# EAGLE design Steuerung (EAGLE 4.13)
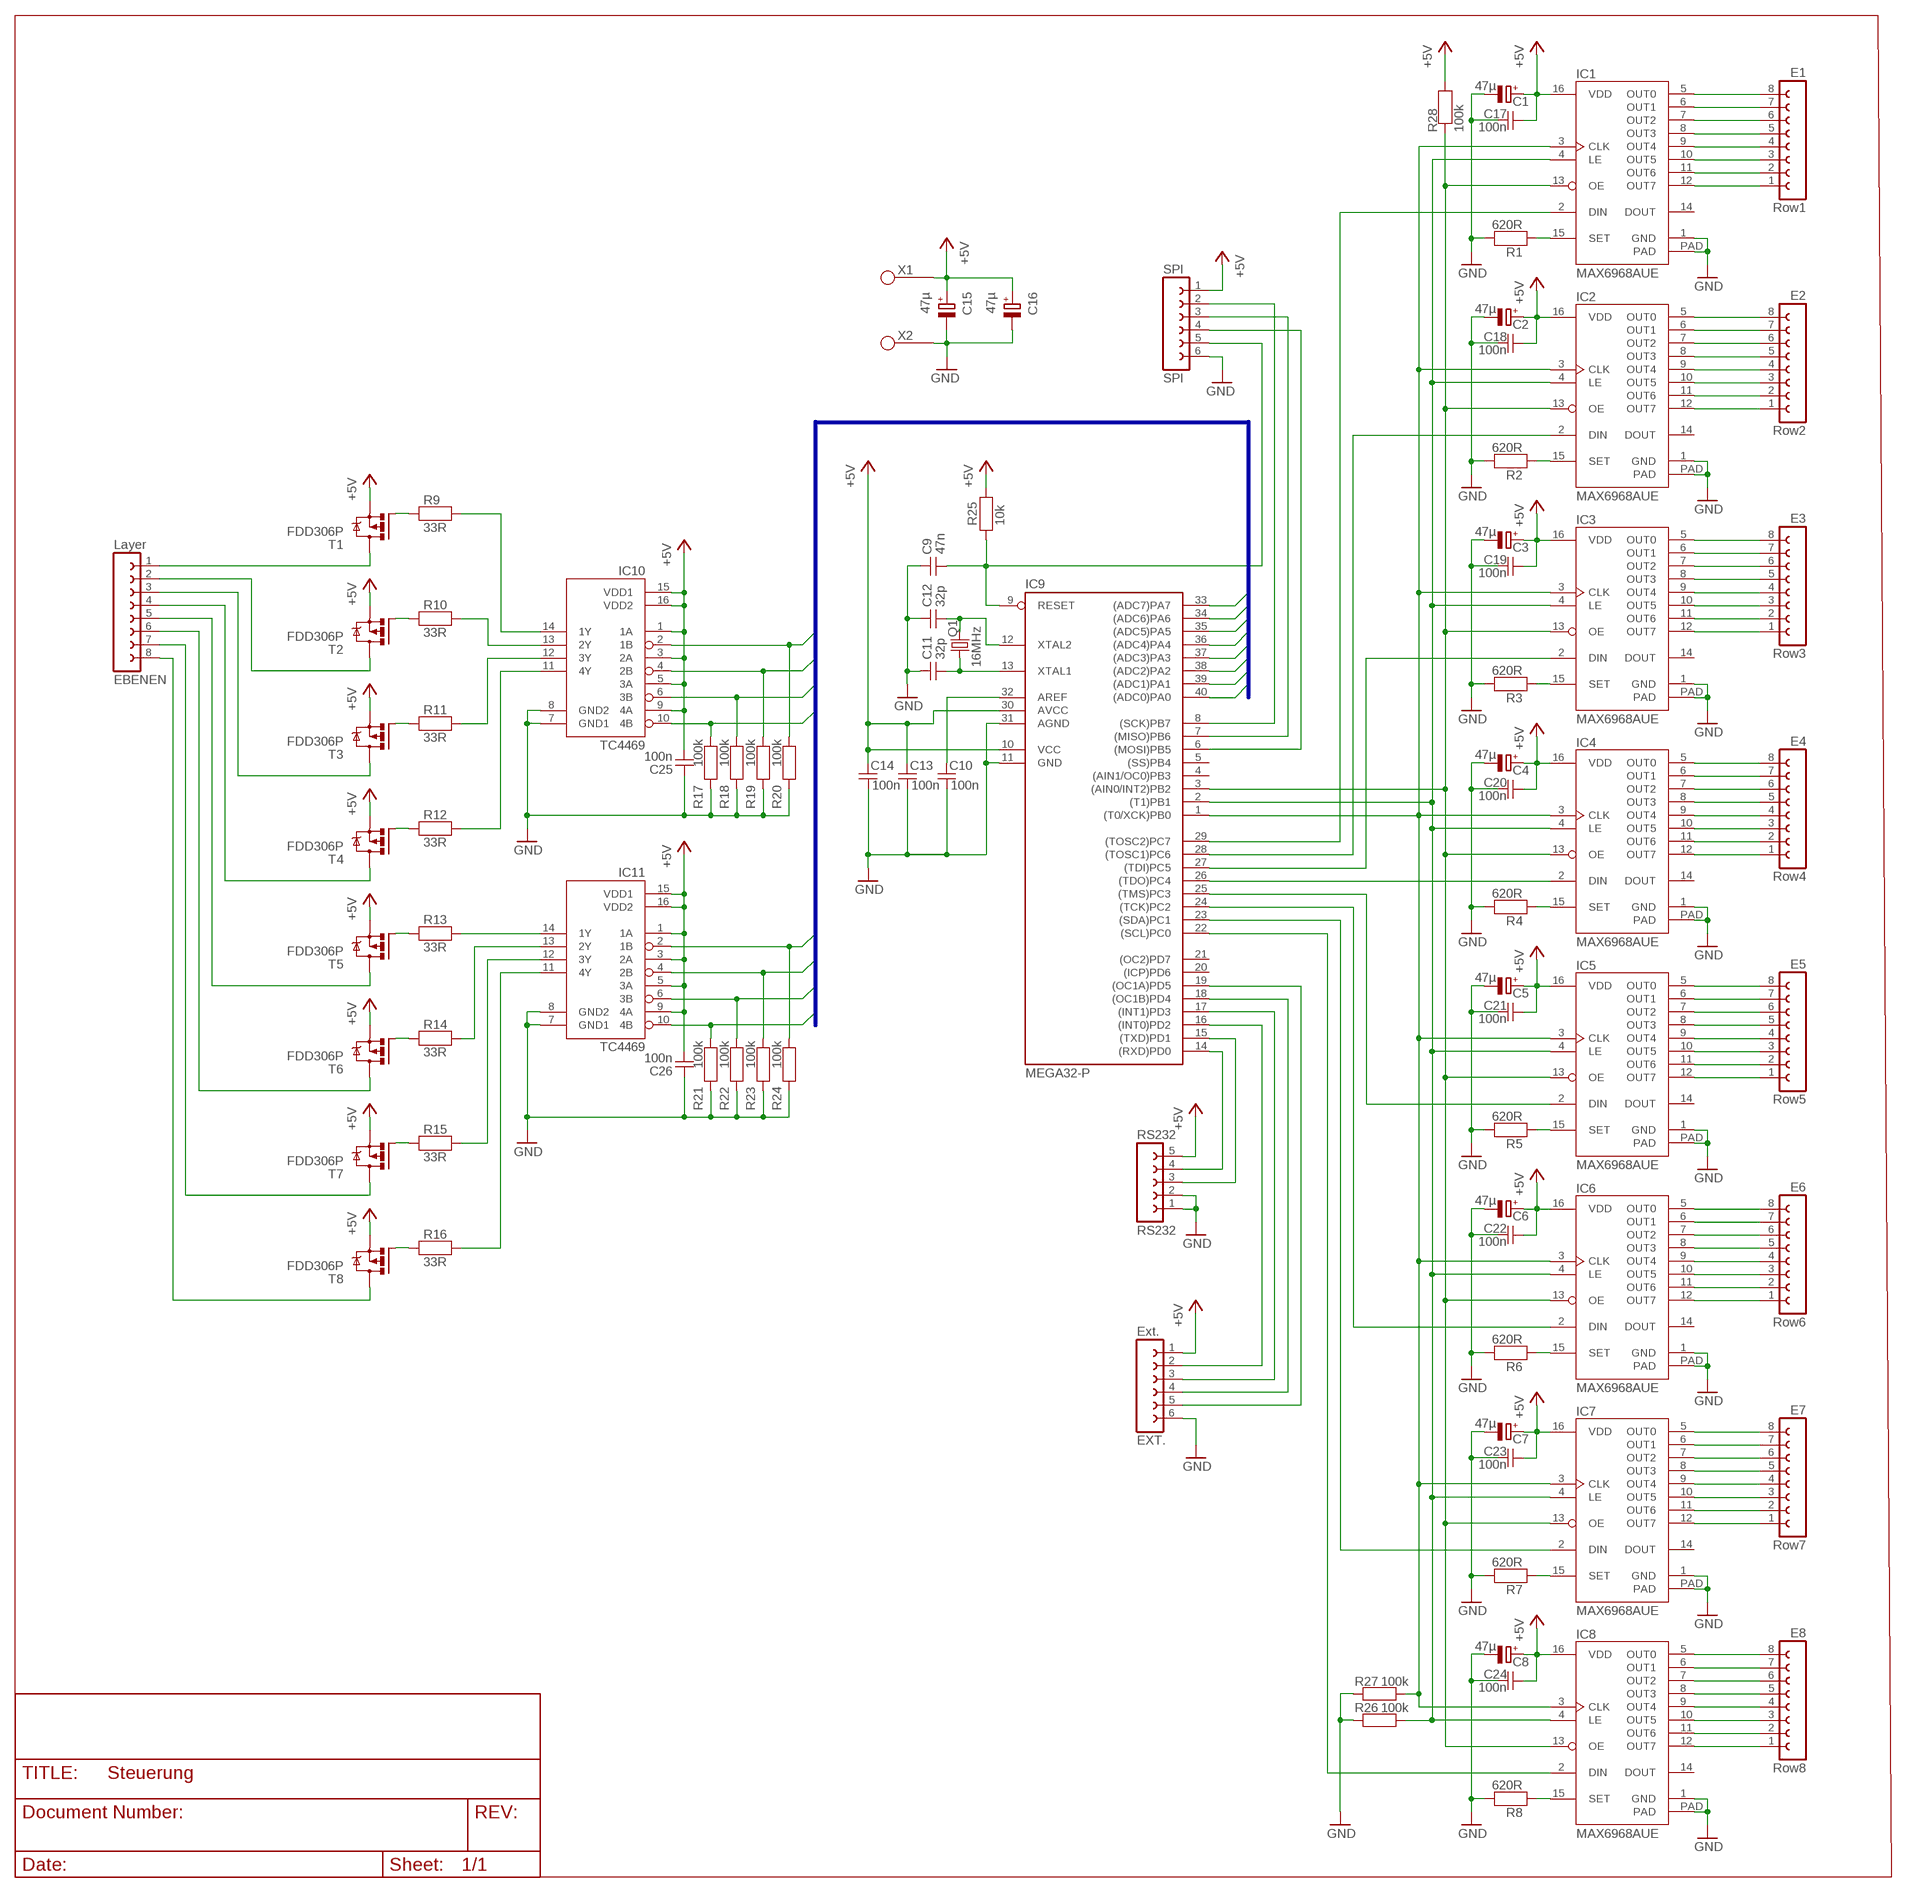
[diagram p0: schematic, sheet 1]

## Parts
C1  47µ  CPOL-EU153CLV-0505  [153CLV-0505]
C2  47µ  CPOL-EU153CLV-0505  [153CLV-0505]
C3  47µ  CPOL-EU153CLV-0505  [153CLV-0505]
C4  47µ  CPOL-EU153CLV-0505  [153CLV-0505]
C5  47µ  CPOL-EU153CLV-0505  [153CLV-0505]
C6  47µ  CPOL-EU153CLV-0505  [153CLV-0505]
C7  47µ  CPOL-EU153CLV-0505  [153CLV-0505]
C8  47µ  CPOL-EU153CLV-0505  [153CLV-0505]
C9  47n  C_SMD_0805  [SMD_0805]
C10  100n  C_SMD_0805  [SMD_0805]
C11  32p  C_SMD_0805  [SMD_0805]
C12  32p  C_SMD_0805  [SMD_0805]
C13  100n  C_SMD_0805  [SMD_0805]
C14  100n  C_SMD_0805  [SMD_0805]
C15  47µ  CPOL-EU153CLV-0505  [153CLV-0505]
C16  47µ  CPOL-EU153CLV-0505  [153CLV-0505]
C17  100n  C_SMD_0805  [SMD_0805]
C18  100n  C_SMD_0805  [SMD_0805]
C19  100n  C_SMD_0805  [SMD_0805]
C20  100n  C_SMD_0805  [SMD_0805]
C21  100n  C_SMD_0805  [SMD_0805]
C22  100n  C_SMD_0805  [SMD_0805]
C23  100n  C_SMD_0805  [SMD_0805]
C24  100n  C_SMD_0805  [SMD_0805]
C25  100n  C_SMD_0805  [SMD_0805]
C26  100n  C_SMD_0805  [SMD_0805]
E1  Row1  FE08W  [FE08W]
E2  Row2  FE08W  [FE08W]
E3  Row3  FE08W  [FE08W]
E4  Row4  FE08W  [FE08W]
E5  Row5  FE08W  [FE08W]
E6  Row6  FE08W  [FE08W]
E7  Row7  FE08W  [FE08W]
E8  Row8  FE08W  [FE08W]
EBENEN  Layer  FE08W  [FE08W]
EXT.  Ext.  FE06W  [FE06W]
IC1  MAX6968AUE  MAX6968  [TSSOP16_EP]
IC2  MAX6968AUE  MAX6968  [TSSOP16_EP]
IC3  MAX6968AUE  MAX6968  [TSSOP16_EP]
IC4  MAX6968AUE  MAX6968  [TSSOP16_EP]
IC5  MAX6968AUE  MAX6968  [TSSOP16_EP]
IC6  MAX6968AUE  MAX6968  [TSSOP16_EP]
IC7  MAX6968AUE  MAX6968  [TSSOP16_EP]
IC8  MAX6968AUE  MAX6968  [TSSOP16_EP]
IC9  MEGA32-P  [DIL40]
IC10  TC4469  TC4496_SOIC  [SO16L]
IC11  TC4469  TC4496_SOIC  [SO16L]
Q1  16MHz  CRYSTALHC49UP  [HC49UP]
R1  620R  R_SMD_0805  [SMD_0805]
R2  620R  R_SMD_0805  [SMD_0805]
R3  620R  R_SMD_0805  [SMD_0805]
R4  620R  R_SMD_0805  [SMD_0805]
R5  620R  R_SMD_0805  [SMD_0805]
R6  620R  R_SMD_0805  [SMD_0805]
R7  620R  R_SMD_0805  [SMD_0805]
R8  620R  R_SMD_0805  [SMD_0805]
R9  33R  R_SMD_0805  [SMD_0805]
R10  33R  R_SMD_0805  [SMD_0805]
R11  33R  R_SMD_0805  [SMD_0805]
R12  33R  R_SMD_0805  [SMD_0805]
R13  33R  R_SMD_0805  [SMD_0805]
R14  33R  R_SMD_0805  [SMD_0805]
R15  33R  R_SMD_0805  [SMD_0805]
R16  33R  R_SMD_0805  [SMD_0805]
R17  100k  R_SMD_0805  [SMD_0805]
R18  100k  R_SMD_0805  [SMD_0805]
R19  100k  R_SMD_0805  [SMD_0805]
R20  100k  R_SMD_0805  [SMD_0805]
R21  100k  R_SMD_0805  [SMD_0805]
R22  100k  R_SMD_0805  [SMD_0805]
R23  100k  R_SMD_0805  [SMD_0805]
R24  100k  R_SMD_0805  [SMD_0805]
R25  10k  R_SMD_0805  [SMD_0805]
R26  100k  R_SMD_0805  [SMD_0805]
R27  100k  R_SMD_0805  [SMD_0805]
R28  100k  R_SMD_0805  [SMD_0805]
RS232  RS232  FE05W  [FE05W]
SPI  SPI  FE06W  [FE06W]
T1  FDD306P  MOSFET-P  [DPAK]
T2  FDD306P  MOSFET-P  [DPAK]
T3  FDD306P  MOSFET-P  [DPAK]
T4  FDD306P  MOSFET-P  [DPAK]
T5  FDD306P  MOSFET-P  [DPAK]
T6  FDD306P  MOSFET-P  [DPAK]
T7  FDD306P  MOSFET-P  [DPAK]
T8  FDD306P  MOSFET-P  [DPAK]
X1  LOETANSCHLUSS_1,0  [LOETANSCHLUSS_1,0]
X2  LOETANSCHLUSS_1,0  [LOETANSCHLUSS_1,0]

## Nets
+5V: C1.+ C2.+ C3.+ C4.+ C5.+ C6.+ C7.+ C8.+ C13.1 C14.1 C15.+ C16.+ C17.2 C18.2 C19.2 C20.2 C21.2 C22.2 C23.2 C24.2 C25.2 C26.2 EXT..1 IC1.16(VDD) IC2.16(VDD) IC3.16(VDD) IC4.16(VDD) IC5.16(VDD) IC6.16(VDD) IC7.16(VDD) IC8.16(VDD) IC9.10(VCC) IC9.30(AVCC) IC10.1(1A) IC10.3(2A) IC10.5(3A) IC10.9(4A) IC10.15(VDD1) IC10.16(VDD2) IC11.1(1A) IC11.3(2A) IC11.5(3A) IC11.9(4A) IC11.15(VDD1) IC11.16(VDD2) R25.2 R28.2 RS232.5 SPI.1 T1.3(S) T2.3(S) T3.3(S) T4.3(S) T5.3(S) T6.3(S) T7.3(S) T8.3(S) X1.P$1
CLK: IC1.3(CLK) IC2.3(CLK) IC3.3(CLK) IC4.3(CLK) IC5.3(CLK) IC6.3(CLK) IC7.3(CLK) IC8.3(CLK) IC9.1((T0/XCK)PB0) R27.2
E0: IC9.40((ADC0)PA0) IC10.2(1B) R20.2
E1: IC9.39((ADC1)PA1) IC10.4(2B) R19.2
E2: IC9.38((ADC2)PA2) IC10.6(3B) R18.2
E3: IC9.37((ADC3)PA3) IC10.10(4B) R17.2
E4: IC9.36((ADC4)PA4) IC11.2(1B) R24.2
E5: IC9.35((ADC5)PA5) IC11.4(2B) R23.2
E6: IC9.34((ADC6)PA6) IC11.6(3B) R22.2
E7: IC9.33((ADC7)PA7) IC11.10(4B) R21.2
GND: C1.- C2.- C3.- C4.- C5.- C6.- C7.- C8.- C9.1 C10.2 C11.1 C12.1 C13.2 C14.2 C15.- C16.- C17.1 C18.1 C19.1 C20.1 C21.1 C22.1 C23.1 C24.1 C25.1 C26.1 EXT..6 IC1.1(GND) IC1.PAD IC2.1(GND) IC2.PAD IC3.1(GND) IC3.PAD IC4.1(GND) IC4.PAD IC5.1(GND) IC5.PAD IC6.1(GND) IC6.PAD IC7.1(GND) IC7.PAD IC8.1(GND) IC8.PAD IC9.11(GND) IC9.31(AGND) IC10.7(GND1) IC10.8(GND2) IC11.7(GND1) IC11.8(GND2) R1.2 R2.2 R3.2 R4.2 R5.2 R6.2 R7.2 R8.2 R17.1 R18.1 R19.1 R20.1 R21.1 R22.1 R23.1 R24.1 R26.1 R27.1 RS232.1 RS232.2 SPI.6 X2.P$1
LE: IC1.4(LE) IC2.4(LE) IC3.4(LE) IC4.4(LE) IC5.4(LE) IC6.4(LE) IC7.4(LE) IC8.4(LE) IC9.2((T1)PB1) R26.2
MISO: IC9.7((MISO)PB6) SPI.3
MOSI: IC9.6((MOSI)PB5) SPI.4
N$1: EBENEN.1 T1.2(D)
N$2: R9.1 T1.1(G)
N$3: R10.1 T2.1(G)
N$4: EBENEN.2 T2.2(D)
N$5: IC1.15(SET) R1.1
N$6: R11.1 T3.1(G)
N$7: EBENEN.3 T3.2(D)
N$8: R12.1 T4.1(G)
N$9: EBENEN.4 T4.2(D)
N$10: IC3.15(SET) R3.1
N$11: R13.1 T5.1(G)
N$12: EBENEN.5 T5.2(D)
N$13: R14.1 T6.1(G)
N$14: C11.2 IC9.13(XTAL1) Q1.1
N$15: IC4.15(SET) R4.1
N$16: IC1.2(DIN) IC9.29((TOSC2)PC7)
N$17: C12.2 IC9.12(XTAL2) Q1.2
N$18: E1.8 IC1.5(OUT0)
N$19: C10.1 IC9.32(AREF)
N$20: IC2.2(DIN) IC9.28((TOSC1)PC6)
N$21: IC3.2(DIN) IC9.27((TDI)PC5)
N$22: IC4.2(DIN) IC9.26((TDO)PC4)
N$23: IC2.15(SET) R2.1
N$24: IC5.2(DIN) IC9.25((TMS)PC3)
N$25: IC6.2(DIN) IC9.24((TCK)PC2)
N$26: IC5.15(SET) R5.1
N$27: IC7.2(DIN) IC9.23((SDA)PC1)
N$28: IC8.2(DIN) IC9.22((SCL)PC0)
N$29: IC6.15(SET) R6.1
N$30: EBENEN.6 T6.2(D)
N$31: R15.1 T7.1(G)
N$32: IC7.15(SET) R7.1
N$33: IC9.14((RXD)PD0) RS232.4
N$34: IC9.15((TXD)PD1) RS232.3
N$35: IC8.15(SET) R8.1
N$36: EBENEN.7 T7.2(D)
N$37: R16.1 T8.1(G)
N$38: EBENEN.8 T8.2(D)
N$39: IC10.14(1Y) R9.2
N$40: IC10.13(2Y) R10.2
N$41: IC10.12(3Y) R11.2
N$42: IC10.11(4Y) R12.2
N$43: IC11.14(1Y) R13.2
N$44: IC11.13(2Y) R14.2
N$45: IC11.12(3Y) R15.2
N$46: IC11.11(4Y) R16.2
N$47: E1.7 IC1.6(OUT1)
N$48: E1.6 IC1.7(OUT2)
N$49: E1.5 IC1.8(OUT3)
N$50: E1.4 IC1.9(OUT4)
N$51: E1.3 IC1.10(OUT5)
N$52: E1.2 IC1.11(OUT6)
N$53: E1.1 IC1.12(OUT7)
N$54: E2.8 IC2.5(OUT0)
N$55: E2.7 IC2.6(OUT1)
N$56: E2.6 IC2.7(OUT2)
N$57: E2.5 IC2.8(OUT3)
N$58: E2.4 IC2.9(OUT4)
N$59: E2.3 IC2.10(OUT5)
N$60: E2.2 IC2.11(OUT6)
N$61: E2.1 IC2.12(OUT7)
N$62: E3.8 IC3.5(OUT0)
N$63: E3.7 IC3.6(OUT1)
N$64: E3.6 IC3.7(OUT2)
N$65: E3.5 IC3.8(OUT3)
N$66: E3.4 IC3.9(OUT4)
N$67: E3.3 IC3.10(OUT5)
N$68: E3.2 IC3.11(OUT6)
N$69: E3.1 IC3.12(OUT7)
N$70: E4.8 IC4.5(OUT0)
N$71: E4.7 IC4.6(OUT1)
N$72: E4.6 IC4.7(OUT2)
N$73: E4.5 IC4.8(OUT3)
N$74: E4.4 IC4.9(OUT4)
N$75: E4.3 IC4.10(OUT5)
N$76: E4.2 IC4.11(OUT6)
N$77: E4.1 IC4.12(OUT7)
N$78: E5.8 IC5.5(OUT0)
N$79: E5.7 IC5.6(OUT1)
N$80: E5.6 IC5.7(OUT2)
N$81: E5.5 IC5.8(OUT3)
N$82: E5.4 IC5.9(OUT4)
N$83: E5.3 IC5.10(OUT5)
N$84: E5.2 IC5.11(OUT6)
N$85: E5.1 IC5.12(OUT7)
N$86: E6.8 IC6.5(OUT0)
N$87: E6.7 IC6.6(OUT1)
N$88: E6.6 IC6.7(OUT2)
N$89: E6.5 IC6.8(OUT3)
N$90: E6.4 IC6.9(OUT4)
N$91: E6.3 IC6.10(OUT5)
N$92: E6.2 IC6.11(OUT6)
N$93: E6.1 IC6.12(OUT7)
N$94: E7.7 IC7.6(OUT1)
N$95: E7.8 IC7.5(OUT0)
N$96: E7.6 IC7.7(OUT2)
N$97: E7.5 IC7.8(OUT3)
N$98: E7.4 IC7.9(OUT4)
N$99: E7.3 IC7.10(OUT5)
N$100: E7.2 IC7.11(OUT6)
N$101: E7.1 IC7.12(OUT7)
N$102: E8.8 IC8.5(OUT0)
N$103: E8.7 IC8.6(OUT1)
N$104: E8.6 IC8.7(OUT2)
N$105: E8.5 IC8.8(OUT3)
N$106: E8.4 IC8.9(OUT4)
N$107: E8.3 IC8.10(OUT5)
N$108: E8.2 IC8.11(OUT6)
N$109: E8.1 IC8.12(OUT7)
N$112: EXT..2 IC9.16((INT0)PD2)
N$113: EXT..3 IC9.17((INT1)PD3)
N$114: EXT..4 IC9.18((OC1B)PD4)
N$115: EXT..5 IC9.19((OC1A)PD5)
OE: IC1.13(OE) IC2.13(OE) IC3.13(OE) IC4.13(OE) IC5.13(OE) IC6.13(OE) IC7.13(OE) IC8.13(OE) IC9.3((AIN0/INT2)PB2) R28.1
RESET: C9.2 IC9.9(RESET) R25.1 SPI.5
SCK: IC9.8((SCK)PB7) SPI.2
Unconnected: IC1.14(DOUT) IC2.14(DOUT) IC3.14(DOUT) IC4.14(DOUT) IC5.14(DOUT) IC6.14(DOUT) IC7.14(DOUT) IC8.14(DOUT) IC9.4((AIN1/OC0)PB3) IC9.5((SS)PB4) IC9.20((ICP)PD6) IC9.21((OC2)PD7)

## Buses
EBENEN:E[0..7]

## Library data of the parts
C1-C8 C15 C16 = rcl:CPOL-EU: POLARIZED CAPACITOR, European symbol
C9-C14 C17-C26 = LEMF-passiv:C: KONDENSATOR
E1-E8 EBENEN = con-lsta:FE08W: FEMALE HEADER
EXT. SPI = con-lsta:FE06W: FEMALE HEADER
IC1-IC8 = maxim:MAX6968
IC9 = avr-5-4.16:MEGA32-P: MICROCONTROLLER 32 Kbytes FLASH 2 Kbytes SRAM 1 Kbytes EEPROM USART 8-channel 10 bit ADC
IC10 IC11 = microchip:TC4496_SOIC
Q1 = LEMF-Mix:CRYSTAL: CRYSTAL
R1-R28 = LEMF-passiv:R: Widerstand
RS232 = con-lsta:FE05W: FEMALE HEADER
T1-T8 = transistor-fet:MOSFET-P
X1 X2 = LEMF-Con:LOETANSCHLUSS

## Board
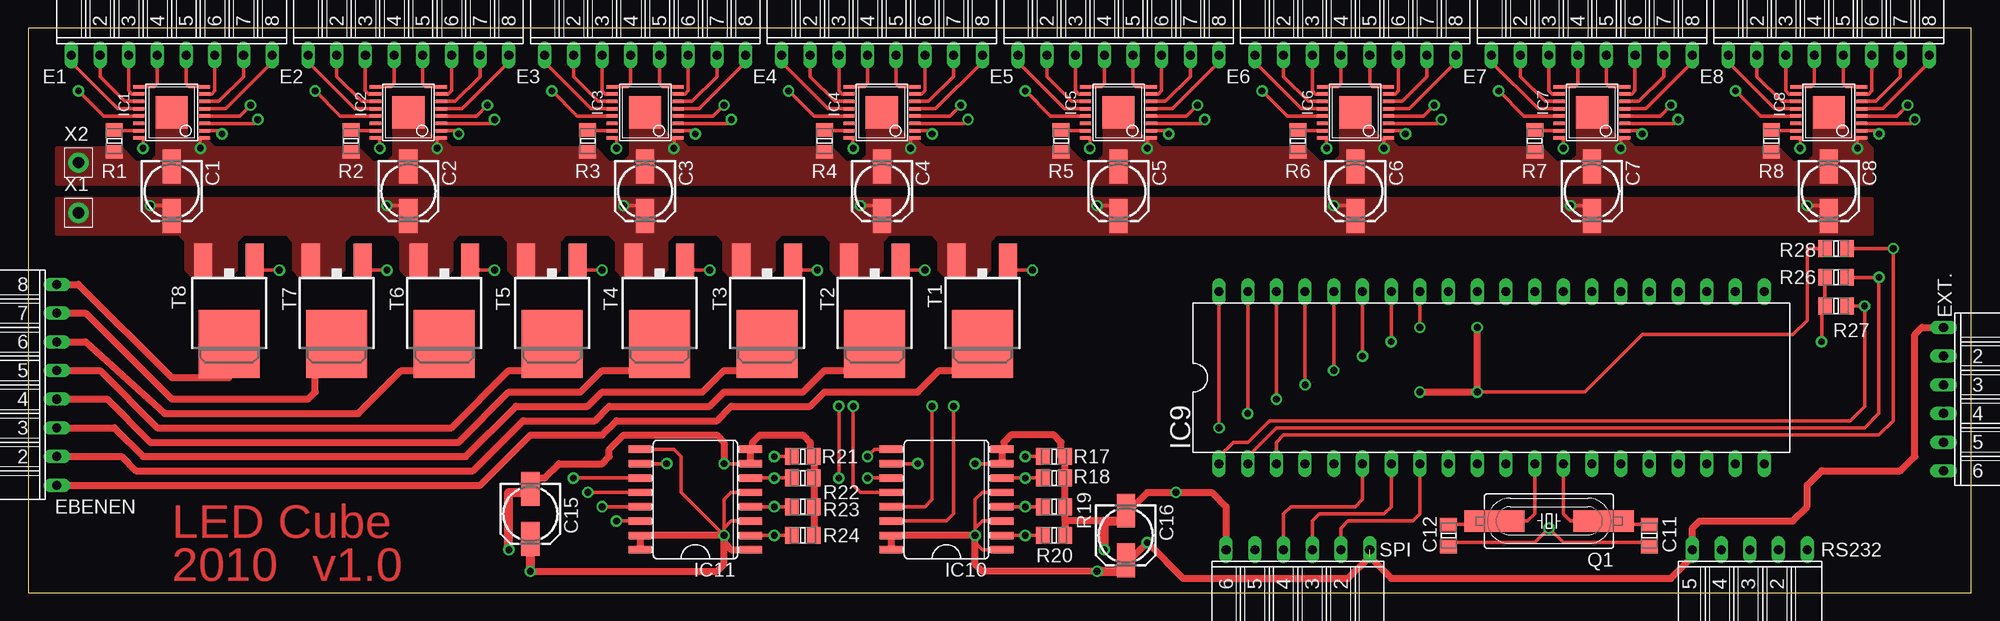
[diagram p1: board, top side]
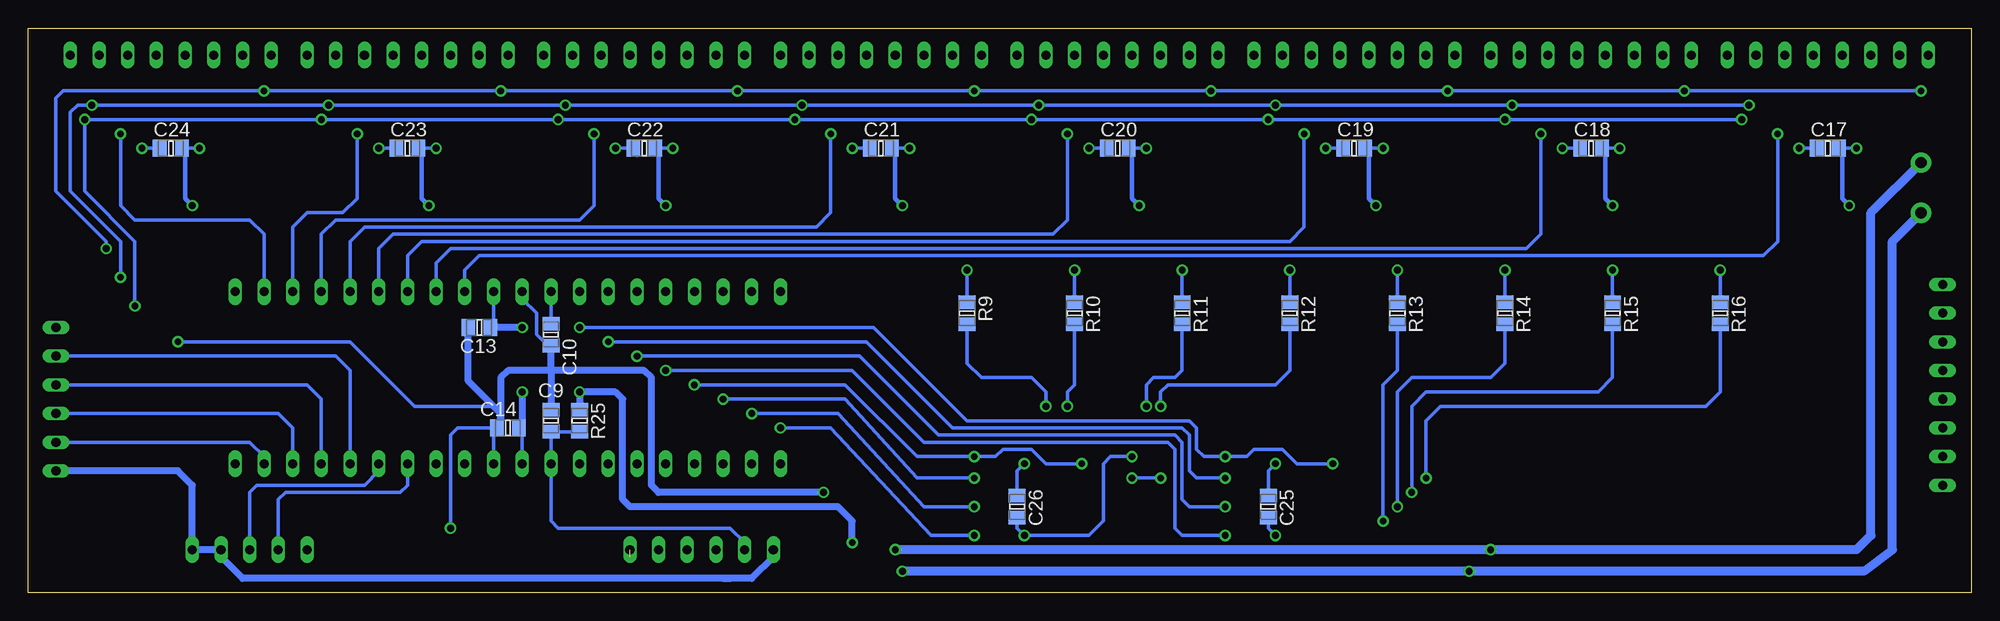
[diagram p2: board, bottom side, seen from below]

Size 172 x 50 mm. Coordinates in mm from the lower left corner, seen from the top.
Outline: 0,0 172,0 172,50 0,50 0,0
Copper layers (1*16): Top 0.035mm / dielectric 1.5mm / Bottom 0.035mm
Design rules "qp_designrules_8mil": minimum track width 8mil, minimum drill 20mil, track to track 8mil, track to pad 8mil, pad to pad 8mil, via to via 8mil, smd to smd 8mil, copper to edge 20mil, drill to drill 20mil, minimum pad ring 8mil, minimum via ring 8mil, stop-mask expansion 0mil, vias tented up to drill 0mil, thermal gap 10mil

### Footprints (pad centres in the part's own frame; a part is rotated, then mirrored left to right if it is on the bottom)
153CLV-0505 = smd 3 x 1.6: + 2.2,0; - -2.2,0
SMD_0805 = smd 1.2 x 1.5: 1 -0.975,0; 2 0.975,0
FE08W = drill 0.8 long: 1 -8.89,0; 2 -6.35,0; 3 -3.81,0; 4 -1.27,0; 5 1.27,0; 6 3.81,0; 7 6.35,0; 8 8.89,0
FE06W = drill 0.8 long: 1 -6.35,0; 2 -3.81,0; 3 -1.27,0; 4 1.27,0; 5 3.81,0; 6 6.35,0
TSSOP16_EP = smd 0.305 x 0.991: 1 -2.275,-2.918; 2 -1.625,-2.918; 3 -0.975,-2.918; 4 -0.325,-2.918; 5 0.325,-2.918; 6 0.975,-2.918; 7 1.625,-2.918; 8 2.275,-2.918; 9 2.275,2.918; 10 1.625,2.918; 11 0.975,2.918; 12 0.325,2.918; 13 -0.325,2.918; 14 -0.975,2.918; 15 -1.625,2.918; 16 -2.275,2.918 | smd 2.85 x 2.85: PAD 0,0
DIL40 = drill 0.8 long: 1 -24.13,-7.62; 2 -21.59,-7.62; 3 -19.05,-7.62; 4 -16.51,-7.62; 5 -13.97,-7.62; 6 -11.43,-7.62; 7 -8.89,-7.62; 8 -6.35,-7.62; 9 -3.81,-7.62; 10 -1.27,-7.62; 11 1.27,-7.62; 12 3.81,-7.62; 13 6.35,-7.62; 14 8.89,-7.62; 15 11.43,-7.62; 16 13.97,-7.62; 17 16.51,-7.62; 18 19.05,-7.62; 19 21.59,-7.62; 20 24.13,-7.62; 21 24.13,7.62; 22 21.59,7.62; 23 19.05,7.62; 24 16.51,7.62; 25 13.97,7.62; 26 11.43,7.62; 27 8.89,7.62; 28 6.35,7.62; 29 3.81,7.62; 30 1.27,7.62; 31 -1.27,7.62; 32 -3.81,7.62; 33 -6.35,7.62; 34 -8.89,7.62; 35 -11.43,7.62; 36 -13.97,7.62; 37 -16.51,7.62; 38 -19.05,7.62; 39 -21.59,7.62; 40 -24.13,7.62
SO16L = smd 0.66 x 2.032: 1 -4.445,-4.902; 2 -3.175,-4.902; 3 -1.905,-4.902; 4 -0.635,-4.902; 5 0.635,-4.902; 6 1.905,-4.902; 7 3.175,-4.902; 8 4.445,-4.902; 9 4.445,4.902; 10 3.175,4.902; 11 1.905,4.902; 12 0.635,4.902; 13 -0.635,4.902; 14 -1.905,4.902; 15 -3.175,4.902; 16 -4.445,4.902
HC49UP = smd 5.334 x 1.93: 1 -4.826,0; 2 4.826,0
FE05W = drill 0.8 long: 1 -5.08,0; 2 -2.54,0; 3 0,0; 4 2.54,0; 5 5.08,0
DPAK = smd 1.6 x 3: 1 -2.28,-5.31; 3 2.28,-5.31 | smd 5.4 x 6: 2 0,2.096
LOETANSCHLUSS_1,0 = drill 1 pad 1.8 round: P$1 0,0

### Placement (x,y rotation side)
C1  12.7,35.56 270 top
C2  33.66,35.56 270 top
C3  54.61,35.56 270 top
C4  75.56,35.56 270 top
C5  96.52,35.56 270 top
C6  117.47,35.56 270 top
C7  138.43,35.56 270 top
C8  159.38,35.56 270 top
C9  125.73,15.24 270 bottom
C10  125.73,22.86 270 bottom
C11  143.51,5.08 90 top
C12  125.73,5.08 90 top
C13  132.08,23.5 180 bottom
C14  129.54,14.61 180 bottom
C15  44.45,6.99 270 top
C16  97.16,5.08 270 top
C17  12.7,39.37 0 bottom
C18  33.66,39.37 0 bottom
C19  54.61,39.37 0 bottom
C20  75.56,39.37 0 bottom
C21  96.52,39.37 0 bottom
C22  117.47,39.37 0 bottom
C23  138.43,39.37 0 bottom
C24  159.38,39.37 0 bottom
C25  62.23,7.62 270 bottom
C26  84.45,7.62 270 bottom
E1  12.7,47.62 0 top
E2  33.66,47.62 0 top
E3  54.61,47.62 0 top
E4  75.56,47.62 0 top
E5  96.52,47.62 0 top
E6  117.47,47.62 0 top
E7  138.43,47.62 0 top
E8  159.38,47.62 0 top
EBENEN  2.54,18.41 90 top
EXT.  169.54,17.14 270 top
IC1  12.7,42.55 90 top
IC2  33.66,42.55 90 top
IC3  54.61,42.55 90 top
IC4  75.56,42.55 90 top
IC5  96.52,42.55 90 top
IC6  117.47,42.55 90 top
IC7  138.43,42.55 90 top
IC8  159.38,42.55 90 top
IC9  129.54,19.05 0 top
IC10  81.28,8.26 90 top
IC11  59.05,8.26 90 top
Q1  134.62,6.35 180 top
R1  7.62,40.01 270 top
R2  28.57,40.01 270 top
R3  49.53,40.01 270 top
R4  70.48,40.01 270 top
R5  91.44,40.01 270 top
R6  112.39,40.01 270 top
R7  133.35,40.01 270 top
R8  154.31,40.01 270 top
R9  88.9,24.77 270 bottom
R10  79.38,24.77 270 bottom
R11  69.85,24.77 270 bottom
R12  60.33,24.77 270 bottom
R13  50.8,24.77 270 bottom
R14  41.27,24.77 270 bottom
R15  31.75,24.77 270 bottom
R16  22.23,24.77 270 bottom
R17  90.81,12.06 180 top
R18  90.81,10.16 180 top
R19  90.81,7.62 180 top
R20  90.81,5.08 180 top
R21  68.58,12.06 180 top
R22  68.58,10.16 180 top
R23  68.58,7.62 180 top
R24  68.58,5.08 180 top
R25  123.19,15.24 90 bottom
R26  160.02,27.94 0 top
R27  160.02,25.4 0 top
R28  160.02,30.48 180 top
RS232  152.4,3.81 180 top
SPI  112.39,3.81 180 top
T1  84.45,24.13 180 top
T2  74.93,24.13 180 top
T3  65.41,24.13 180 top
T4  55.88,24.13 180 top
T5  46.35,24.13 180 top
T6  36.83,24.13 180 top
T7  27.3,24.13 180 top
T8  17.78,24.13 180 top
X1  4.45,33.66 0 top
X2  4.45,38.1 0 top

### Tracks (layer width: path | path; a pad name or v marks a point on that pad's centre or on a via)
+5V  (via drill 0.6)  (1 unrouted)
  Top 0.3: IC3.16 52.07,40.27 v52.07,39.37 | IC1.16 10.16,40.27 v10.16,39.37 | IC2.16 31.11,40.27 v31.11,39.37 | IC4.16 73.03,40.27 v73.03,39.37 | IC5.16 93.98,40.27 v93.98,39.37 | IC6.16 114.94,40.27 v114.94,39.37 | IC7.16 135.89,40.27 v135.89,39.37 | IC8.16 156.84,40.27 v156.84,39.37 | v10.79,34.29 12.7,34.29 | v31.75,34.29 33.66,34.29 C2.+ 33.66,33.02 | v52.7,34.29 54.61,34.29 C3.+ | v73.66,34.29 75.56,34.29 C4.+ 75.56,33.02 | v94.61,34.29 96.52,34.29 C5.+ 96.52,33.02 | v115.57,34.29 117.47,34.29 C6.+ 117.47,33.02 | v136.53,34.29 138.43,34.29 C7.+ 138.43,33.02 | v157.48,34.29 159.38,34.29 C8.+ 159.38,33.02 | IC11.15 53.98,5.08 | IC11.16 54.61,3.81 | 54.61,12.7 IC11.9 57.15,12.7 57.78,12.06 57.78,8.89 v61.59,5.08 | IC11.3 62.23,6.35 61.59,5.71 v61.59,5.08 | IC11.5 62.23,8.89 61.59,8.26 v61.59,5.08 | IC10.15 76.2,5.08 76.38,4.9 | IC10.1 84.45,3.81 83.82,4.45 v83.82,5.08 | IC10.3 84.45,6.35 83.82,5.71 v83.82,5.08 | IC10.5 84.45,8.89 83.82,8.26 v83.82,5.08 | v74.3,12.06 74.93,12.7 IC10.9 | R28.2 157.48,30.48 157.48,24.13 156.21,22.86 142.88,22.86 137.79,17.78 v128.27,17.78
  Top 0.6: v61.59,5.08 IC11.15 IC11.16 | IC11.1 62.23,3.81 61.59,4.45 v61.59,5.08 | 76.38,4.9 IC10.16 | IC10.15 v83.82,5.08 83.82,2.54 84.45,1.91 v94.61,1.91 | C15.+ 44.45,5.08 | v61.59,5.08 61.59,2.54 60.96,1.91 v44.45,1.91 | v123.19,17.78 v128.27,17.78 v128.27,23.5 | C16.+ 97.5,2.88 v99.06,4.45 102.23,1.27 116.84,1.27 118.75,3.17 120.65,1.27 145.41,1.27 147.32,3.17 RS232.5 147.32,5.71 147.96,6.35 156.21,6.35 157.48,7.62 157.48,9.53 158.75,10.79 165.74,10.79 167,12.06 167,22.86 167.64,23.5 EXT..1
  Top 0.8: v94.61,1.91 97.16,1.91 C16.+ | v44.45,1.91 C15.+
  Bottom 0.3: 95.89,39.37 C21.2 95.25,39.37 v93.98,39.37 | v52.07,39.37 53.34,39.37 C19.2 | 12.06,39.37 C17.2 11.43,39.37 v10.16,39.37 | 33.02,39.37 C18.2 32.38,39.37 v31.11,39.37 | 74.93,39.37 C20.2 74.3,39.37 v73.03,39.37 | v114.94,39.37 116.2,39.37 C22.2 | 137.79,39.37 C23.2 137.16,39.37 v135.89,39.37 | 158.75,39.37 C24.2 158.12,39.37 v156.84,39.37 | C25.2 62.23,5.71 v61.59,5.08 | 84.45,6.99 C26.2 84.45,5.71 v83.82,5.08 78.11,5.08 76.83,6.35 76.83,11.43 76.2,12.06 v74.3,12.06 | C14.1 128.27,14.61 IC9.10 | 130.81,23.5 IC9.30
  Bottom 0.4: v10.79,34.29 11.43,34.92 11.43,39.37 | v31.75,34.29 32.38,34.92 32.38,39.37 | v52.7,34.29 53.34,34.92 53.34,39.37 | v73.66,34.29 74.3,34.92 74.3,39.37 | v94.61,34.29 95.25,34.92 95.25,39.37 | v115.57,34.29 116.2,34.92 116.2,39.37 | v136.53,34.29 137.16,34.92 137.16,39.37 | v157.48,34.29 158.12,34.92 158.12,39.37
  Bottom 0.6: v128.27,17.78 128.27,14.61 | C13.1 130.81,23.5 v128.27,23.5 | R25.2 v123.19,17.78 120.02,17.78 119.38,17.14 119.38,8.26 118.75,7.62 100.33,7.62 99.06,6.35 v99.06,4.45
  Bottom 0.8: X1.P$1 6.99,31.11 6.99,3.81 9.53,1.91 v44.45,1.91 v94.61,1.91
  pour Top (no thermals): 2.54,34.92 163.19,34.92 163.19,31.75 2.54,31.75
  pour Top (no thermals): 24.13,27.94 23.5,28.57 23.5,31.11 22.86,31.75 19.05,31.75 18.41,31.11 18.41,28.57 17.78,27.94 14.61,27.94 13.97,28.57 13.97,31.11 13.34,31.75 6.99,31.75 6.99,32.38 85.72,32.38 85.72,31.75 85.09,31.11 85.09,28.57 84.45,27.94 81.28,27.94 80.64,28.57 80.64,31.11 80.01,31.75 76.2,31.75 75.56,31.11 75.56,28.57 74.93,27.94 71.75,27.94 71.12,28.57 71.12,31.11 70.48,31.75 66.67,31.75 66.04,31.11 66.04,28.57 65.41,27.94 62.23,27.94 61.59,28.57 61.59,31.11 60.96,31.75 57.15,31.75 56.52,31.11 56.52,28.57 55.88,27.94 52.7,27.94 52.07,28.57 52.07,31.11 51.44,31.75 47.62,31.75 46.99,31.11 46.99,28.57 46.35,27.94 43.18,27.94 42.55,28.57 42.55,31.11 41.91,31.75 38.1,31.75 37.47,31.11 37.47,28.57 36.83,27.94 33.66,27.94 33.02,28.57 33.02,31.11 32.38,31.75 28.57,31.75 27.94,31.11 27.94,28.57 27.3,27.94
CLK  (via drill 0.6, 0.6 pad 0.45)
  Top 0.3: IC1.3 19.98,41.57 v20.32,41.91 | IC2.3 40.94,41.57 v41.27,41.91 | IC3.3 61.89,41.57 v62.23,41.91 | IC4.3 82.84,41.57 v83.19,41.91 | IC5.3 103.8,41.57 v104.14,41.91 | IC6.3 124.75,41.57 v125.09,41.91 | IC7.3 145.71,41.57 v146.05,41.91 | IC8.3 166.66,41.57 v167,41.91 | IC9.1 105.41,12.06 106.68,13.34 107.95,13.34 109.86,15.24 161.29,15.24 162.56,16.51 v162.56,25.4 R27.2
  Bottom 0.3: v20.32,41.91 v41.27,41.91 v62.23,41.91 v83.19,41.91 v104.14,41.91 v125.09,41.91 v146.05,41.91 v167,41.91 167,35.56 162.56,31.11 v162.56,25.4
E0  (via drill 0.6)
  Top 0.3: 90.17,5.08 R20.2 v88.27,5.08 IC10.2 | v105.41,14.61 IC9.40
  Bottom 0.3: v88.27,5.08 92.08,5.08 100.97,14.61 v105.41,14.61
E1  (via drill 0.6)
  Top 0.3: 90.17,7.62 R19.2 v88.27,7.62 IC10.4 | v107.95,15.88 IC9.39
  Bottom 0.3: v88.27,7.62 92.71,7.62 100.33,15.88 v107.95,15.88
E2  (via drill 0.6)
  Top 0.3: 90.17,10.16 R18.2 v88.27,10.16 IC10.6 | v110.49,17.14 IC9.38
  Bottom 0.3: v88.27,10.16 93.34,10.16 99.69,17.14 v110.49,17.14
E3  (via drill 0.6)
  Top 0.3: v88.27,12.06 R17.2 | 76.2,11.43 IC10.10 v78.74,11.43 | v113.03,18.41 IC9.37
  Bottom 0.3: v78.74,11.43 81.92,11.43 83.19,12.7 85.72,12.7 86.36,12.06 v88.27,12.06 93.34,12.06 99.69,18.41 v113.03,18.41
E4  (via drill 0.6)
  Top 0.3: IC11.2 v66.04,5.08 R24.2 | v115.57,19.68 IC9.36
  Bottom 0.3: v66.04,5.08 69.85,5.08 70.48,5.71 70.48,12.7 71.12,13.34 92.71,13.34 99.06,19.68 v115.57,19.68
E5  (via drill 0.6)
  Top 0.3: IC11.4 v66.04,7.62 R23.2 67.94,7.62 | v118.11,20.95 IC9.35
  Bottom 0.3: v66.04,7.62 69.22,7.62 69.85,8.26 69.85,13.34 70.48,13.97 91.44,13.97 98.42,20.95 v118.11,20.95
E6  (via drill 0.6)
  Top 0.3: IC11.6 v66.04,10.16 R22.2 67.94,10.16 | v120.65,22.23 IC9.34
  Bottom 0.3: v66.04,10.16 68.58,10.16 69.22,10.79 69.22,13.97 69.85,14.61 90.17,14.61 97.79,22.23 v120.65,22.23
E7  (via drill 0.6)
  Top 0.3: v66.04,12.06 R21.2 | 53.98,11.43 IC11.10 v56.52,11.43 | v123.19,23.5 IC9.33
  Bottom 0.3: v56.52,11.43 59.69,11.43 60.96,12.7 63.5,12.7 64.14,12.06 v66.04,12.06 67.94,12.06 68.58,12.7 68.58,14.61 69.22,15.24 88.9,15.24 97.16,23.5 v123.19,23.5
GND  (via drill 0.6)
  Top 0.3: IC3.1 57.15,40.27 v57.15,39.37 | IC1.1 15.24,40.27 v15.24,39.37 | IC2.1 36.2,40.27 v36.2,39.37 | IC4.1 78.11,40.27 v78.11,39.37 | IC5.1 99.06,40.27 v99.06,39.37 | IC6.1 120.02,40.27 v120.02,39.37 | IC7.1 140.97,40.27 v140.97,39.37 | IC8.1 161.93,40.27 v161.93,39.37 | 64.14,12.7 IC11.8 63.5,12.7 | 64.14,11.43 IC11.7 v61.59,11.43 | 86.18,11.61 86.36,11.43 IC10.7 v83.82,11.43 | 159.38,25.4 R27.1 | R26.1 159.04,25.74 159.38,25.4 | C11.1 143.51,4.45 135.89,4.45 v134.62,5.71 133.35,4.45 125.73,4.45 C12.1 | 159.38,25.4 158.75,25.4 v158.75,22.23 | 85.72,12.7 IC10.8 86.36,12.7 | R17.1 91.44,12.06 | 44.45,8.89 44.45,10.16
  Top 0.6: IC11.7 IC11.8 | IC10.8 86.18,11.61 | 64.14,12.7 64.14,13.34 64.77,13.97 68.58,13.97 69.22,13.34 69.22,12.06 R21.1 69.56,10.46 69.85,10.16 R22.1 69.56,7.96 69.85,7.62 R23.1 69.56,5.42 69.85,5.08 R24.1 | R17.1 91.78,10.5 92.08,10.16 R18.1 91.78,7.96 92.08,7.62 R19.1 91.78,6.35 | R20.1 92.08,5.08 91.78,5.38 91.78,6.35 | 95.25,6.35 91.78,6.35 | 44.45,10.16 45.72,10.16 46.99,11.43 50.8,11.43 51.44,12.06 51.44,12.7 52.7,13.97 60.96,13.97 61.59,13.34 v61.59,11.43 | 86.36,12.7 86.36,13.34 87,13.97 90.81,13.97 91.44,13.34 91.44,12.06 | C11.1 143.51,3.81 143.22,4.11 | 97.16,6.99 99.06,8.89 v101.6,8.89 104.78,8.89 106.05,7.62 SPI.6
  Top 0.8: v42.55,3.81 42.55,8.89 44.45,8.89 C15.- 44.45,9.53 | v95.25,3.81 95.25,6.35 97.16,6.35 97.16,6.99 C16.-
  Bottom 0.3: 55.24,39.37 C19.1 v57.15,39.37 | 13.34,39.37 C17.1 v15.24,39.37 | 34.29,39.37 C18.1 v36.2,39.37 | 76.2,39.37 C20.1 v78.11,39.37 | 97.16,39.37 C21.1 v99.06,39.37 | 118.11,38.73 C22.1 v120.02,39.37 | 139.06,39.37 C23.1 v140.97,39.37 | 160.02,39.37 C24.1 v161.93,39.37 | C25.1 62.23,10.79 v61.59,11.43 | v83.82,11.43 84.45,10.79 C26.1 84.45,8.26 | 130.81,14.61 IC9.11 | v134.62,5.71 134.62,13.97 133.99,14.61 C14.2 130.18,14.61 | v158.75,22.23 143.51,22.23 137.79,16.51 130.18,16.51 | C10.2 126.03,21.89 127,22.86 127,24.77 128.27,26.04 IC9.31
  Bottom 0.6: 125.73,19.68 C9.1 | 125.73,19.68 C10.2 | C14.2 130.81,14.61 130.18,15.24 | 130.18,15.24 130.18,15.88 133.06,18.75 C13.2 | 125.73,19.68 129.54,19.68 130.18,19.05 130.18,16.51 130.18,15.24 | 125.73,19.68 117.47,19.68 116.84,19.05 116.84,9.53 116.2,8.89 v101.6,8.89 | 110.49,1.27 109.86,1.27 | 110.49,1.27 153.03,1.27 154.94,3.17 RS232.2 RS232.1 157.48,9.53 158.75,10.79 EXT..6 | SPI.6 106.05,3.17 107.95,1.27 110.49,1.27
  Bottom 0.8: v95.25,3.81 v42.55,3.81 10.16,3.81 8.89,5.08 8.89,33.66 X2.P$1
  pour Top (no thermals): 11.43,43.81 13.97,43.81 13.97,40.01 15.88,40.01 16.51,39.37 29.21,39.37 30.48,38.1 31.75,38.1 32.38,38.73 32.38,43.81 34.92,43.81 34.92,41.27 36.2,40.01 36.83,40.01 37.47,39.37 50.16,39.37 51.44,38.1 52.7,38.1 53.34,38.73 53.34,43.81 55.88,43.81 55.88,41.27 57.15,40.01 57.78,40.01 58.42,39.37 71.12,39.37 72.39,38.1 73.66,38.1 74.3,38.73 74.3,43.81 76.83,43.81 76.83,41.27 78.11,40.01 78.74,40.01 79.38,39.37 92.08,39.37 93.34,38.1 94.61,38.1 95.25,38.73 95.25,43.81 97.79,43.81 97.79,41.27 99.06,40.01 99.69,40.01 100.33,39.37 113.03,39.37 114.3,38.1 115.57,38.1 116.2,38.73 116.2,43.81 118.75,43.81 118.75,41.27 120.02,40.01 120.65,40.01 121.28,39.37 133.99,39.37 135.25,38.1 136.53,38.1 137.16,38.73 137.16,43.81 139.7,43.81 139.7,41.27 140.97,40.01 141.6,40.01 142.24,39.37 154.94,39.37 156.21,38.1 157.48,38.1 158.12,38.73 158.12,43.81 160.66,43.81 160.66,41.27 161.93,40.01 162.56,40.01 163.19,39.37 163.19,36.2 2.54,36.2 2.54,39.37 8.26,39.37 9.53,38.1 10.79,38.1 11.43,38.73
LE  (via drill 0.6, 0.6 pad 0.45)
  Top 0.3: IC1.4 18.73,42.22 v19.68,43.18 | IC2.4 39.68,42.22 v40.64,43.18 | IC3.4 60.63,42.22 v61.59,43.18 | IC4.4 81.59,42.22 v82.55,43.18 | IC5.4 102.55,42.22 v103.5,43.18 | IC6.4 123.5,42.22 v124.46,43.18 | IC7.4 144.46,42.22 v145.41,43.18 | IC8.4 165.41,42.22 v166.37,43.18 | IC9.2 107.95,12.06 110.49,14.61 162.56,14.61 163.83,15.88 v163.83,27.94 R26.2
  Bottom 0.3: v19.68,43.18 v40.64,43.18 v61.59,43.18 v82.55,43.18 v103.5,43.18 v124.46,43.18 v145.41,43.18 v166.37,43.18 167.64,43.18 168.28,42.55 168.28,35.56 163.83,31.11 v163.83,27.94
MISO
  Top 0.3: SPI.3 113.67,6.35 114.3,6.99 120.02,6.99 120.65,7.62 IC9.7
MOSI
  Top 0.3: SPI.4 111.12,6.99 111.76,7.62 117.47,7.62 118.11,8.26 IC9.6
N$1
  Top 0.6: 84.45,22.23 82.55,22.23 | EBENEN.1 40.01,9.53 44.45,13.97 50.8,13.97 52.07,15.24 60.96,15.24 62.23,16.51 69.22,16.51 70.48,17.78 78.74,17.78 80.64,19.68 84.45,19.68 84.45,22.23 | 84.45,22.23 T1.2
N$2  (via drill 0.6)
  Top 0.3: v88.9,28.57 86.36,28.57 86.36,29.21 86.59,29.44 T1.1
  Bottom 0.3: 88.9,25.4 R9.1 v88.9,28.57
N$3  (via drill 0.6)
  Top 0.3: T2.1 76.83,29.44 76.83,28.57 v79.38,28.57
  Bottom 0.3: 79.38,25.4 R10.1 v79.38,28.57
N$4
  Top 0.6: EBENEN.2 8.26,12.06 9.53,10.79 39.37,10.79 43.81,15.24 50.16,15.24 51.44,16.51 60.33,16.51 61.59,17.78 68.58,17.78 70.48,19.68 74.93,19.68 T2.2 74.93,22.23
N$5
  Top 0.3: 7.62,41.27 R1.1 7.62,40.92 IC1.15
N$6  (via drill 0.6)
  Top 0.3: T3.1 67.31,29.44 67.31,28.57 v69.85,28.57
  Bottom 0.3: 69.85,25.4 R11.1 v69.85,28.57
N$7
  Top 0.6: 65.41,22.23 63.5,22.23 | EBENEN.3 7.62,14.61 10.16,12.06 38.73,12.06 43.18,16.51 49.53,16.51 50.8,17.78 59.69,17.78 61.59,19.68 65.41,19.68 65.41,22.23 | 65.41,22.23 T3.2
N$8  (via drill 0.6)
  Top 0.3: T4.1 57.78,29.44 57.78,28.57 v60.33,28.57
  Bottom 0.3: 60.33,25.4 R12.1 v60.33,28.57
N$9
  Top 0.6: T4.2 55.88,21.59 53.98,21.59 | EBENEN.4 6.99,17.14 10.79,13.34 38.1,13.34 42.55,17.78 48.9,17.78 50.8,19.68 55.88,19.68 T4.2 | T4.2 55.88,22.23
N$10
  Top 0.3: R3.1 49.53,40.92 | 49.53,40.92 IC3.15 | 49.53,40.92 49.53,40.64
N$11  (via drill 0.6)
  Top 0.3: T5.1 48.26,29.44 48.26,28.57 v50.8,28.57
  Bottom 0.3: 50.8,25.4 R13.1 v50.8,28.57
N$12
  Top 0.6: 46.35,21.59 44.45,21.59 | EBENEN.5 6.35,19.68 11.43,14.61 37.47,14.61 42.55,19.68 46.35,19.68 T5.2 46.35,22.23
  Top 0.8: T5.2 46.35,21.59
N$13  (via drill 0.6)
  Top 0.3: T6.1 38.73,29.44 38.73,28.57 v41.27,28.57
  Bottom 0.3: 41.27,25.4 R14.1 v41.27,28.57
N$14
  Top 0.3: IC9.13 135.89,6.99 136.53,6.35 Q1.1 139.7,6.35 140,6.05 C11.2
N$15
  Top 0.3: R4.1 70.48,40.92 | 70.48,40.92 IC4.15 | 70.48,40.92 70.48,40.64
N$16  (via drill 0.6 pad 0.45)
  Top 0.3: IC1.2 16.86,40.92 v17.14,40.64
  Bottom 0.3: v17.14,40.64 17.14,31.11 18.41,29.84 132.08,29.84 133.35,28.57 IC9.29
N$17
  Top 0.3: IC9.12 133.35,6.99 132.72,6.35 Q1.2 129.54,6.35 129.25,6.05 C12.2
N$18
  Top 0.3: IC1.5 17.47,42.87 21.59,46.99 E1.8
N$19
  Bottom 0.3: C10.1 IC9.32
N$20  (via drill 0.6 pad 0.45)
  Top 0.3: IC2.2 37.82,40.92 v38.1,40.64
  Bottom 0.3: v38.1,40.64 38.1,31.75 39.37,30.48 134.62,30.48 135.89,29.21 IC9.28
N$21  (via drill 0.6 pad 0.45)
  Top 0.3: IC3.2 58.77,40.92 v59.05,40.64
  Bottom 0.3: v59.05,40.64 59.05,32.38 60.33,31.11 137.16,31.11 138.43,29.84 IC9.27
N$22  (via drill 0.6 pad 0.45)
  Top 0.3: IC4.2 79.73,40.92 v80.01,40.64
  Bottom 0.3: v80.01,40.64 80.01,33.02 81.28,31.75 139.7,31.75 140.97,30.48 IC9.26
N$23
  Top 0.3: R2.1 28.57,40.92 | 28.57,40.92 IC2.15 | 28.57,40.92 28.57,40.64
N$24  (via drill 0.6 pad 0.45)
  Top 0.3: IC5.2 100.69,40.92 v100.97,40.64
  Bottom 0.3: v100.97,40.64 100.97,33.66 102.23,32.38 142.24,32.38 143.51,31.11 IC9.25
N$25  (via drill 0.6 pad 0.45)
  Top 0.3: IC6.2 121.64,40.92 v121.92,40.64
  Bottom 0.3: v121.92,40.64 121.92,34.29 123.19,33.02 144.78,33.02 146.05,31.75 IC9.24
N$26
  Top 0.3: R5.1 91.44,40.92 | 91.44,40.92 IC5.15 | 91.44,40.92 91.44,40.64
N$27  (via drill 0.6 pad 0.45)
  Top 0.3: IC7.2 142.59,40.92 v142.88,40.64
  Bottom 0.3: v142.88,40.64 142.88,34.92 144.15,33.66 147.32,33.66 148.59,32.38 IC9.23
N$28  (via drill 0.6 pad 0.45)
  Top 0.3: IC8.2 163.55,40.92 v163.83,40.64
  Bottom 0.3: v163.83,40.64 163.83,34.29 162.56,33.02 152.4,33.02 151.13,31.75 IC9.22
N$29
  Top 0.3: R6.1 112.39,40.92 | 112.39,40.92 IC6.15 | 112.39,40.92 112.39,40.64
N$30
  Top 0.6: EBENEN.6 5.08,22.23 12.06,15.88 29.21,15.88 33.02,19.68 36.83,19.68 T6.2 36.83,22.23
N$31  (via drill 0.6)
  Top 0.3: T7.1 29.21,29.44 29.21,28.57 v31.75,28.57
  Bottom 0.3: 31.75,25.4 R15.1 v31.75,28.57
N$32
  Top 0.3: R7.1 133.35,40.92 | 133.35,40.92 IC7.15 | 133.35,40.92 133.35,40.64
N$33
  Bottom 0.3: IC9.14 138.43,9.53 139.06,8.89 149.22,8.89 149.86,8.26 RS232.4
N$34
  Bottom 0.3: IC9.15 140.97,10.79 142.24,9.53 151.76,9.53 152.4,8.89 RS232.3
N$35
  Top 0.3: R8.1 154.31,40.92 | 154.31,40.92 IC8.15 | 154.31,40.92 154.31,40.64
N$36
  Top 0.6: 27.3,21.59 25.4,21.59 25.4,17.78 24.77,17.14 12.7,17.14 5.08,24.77 EBENEN.7
  Top 0.8: 27.3,21.59 T7.2
N$37  (via drill 0.6)
  Top 0.3: T8.1 19.68,29.44 19.68,28.57 v22.23,28.57
  Bottom 0.3: v22.23,28.57 R16.1
N$38
  Top 0.6: 17.78,20.95 T8.2 17.78,19.05 12.7,19.05 4.45,27.3 EBENEN.8
N$39  (via drill 0.6)
  Top 0.3: IC10.14 81.28,6.35 81.92,6.99 v81.92,16.51
  Bottom 0.3: v81.92,16.51 81.92,17.78 83.19,19.05 87.63,19.05 88.9,20.32 R9.2 88.9,24.13
N$40  (via drill 0.6)
  Top 0.3: IC10.13 79.38,7.62 80.01,8.26 v80.01,16.51
  Bottom 0.3: 79.38,24.13 R10.2 79.38,18.41 80.01,17.78 v80.01,16.51
N$41  (via drill 0.6)
  Top 0.3: IC10.12 73.66,8.89 73.03,9.53 v73.03,16.51
  Bottom 0.3: v73.03,16.51 73.03,18.41 72.39,19.05 70.48,19.05 69.85,19.68 R11.2 69.85,24.13
N$42  (via drill 0.6)
  Top 0.3: v74.3,10.16 IC10.11 | v71.75,16.51 v71.75,10.16
  Bottom 0.3: 60.33,24.13 R12.2 60.33,19.68 61.59,18.41 71.12,18.41 71.75,17.78 v71.75,16.51 | v71.75,10.16 v74.3,10.16
N$43  (via drill 0.6)
  Top 0.3: v52.07,6.35 IC11.14
  Bottom 0.3: v52.07,6.35 52.07,18.41 50.8,19.68 R13.2 50.8,24.13
N$44  (via drill 0.6)
  Top 0.3: v50.8,7.62 IC11.13
  Bottom 0.3: v50.8,7.62 50.8,17.78 49.53,19.05 42.55,19.05 41.27,20.32 R14.2 41.27,24.13
N$45  (via drill 0.6)
  Top 0.3: v49.53,8.89 IC11.12
  Bottom 0.3: v49.53,8.89 49.53,16.51 48.26,17.78 33.02,17.78 31.75,19.05 R15.2 31.75,24.13
N$46  (via drill 0.6)
  Top 0.3: v48.26,10.16 IC11.11
  Bottom 0.3: v48.26,10.16 48.26,15.24 46.99,16.51 23.5,16.51 22.23,17.78 R16.2 22.23,24.13
N$47
  Top 0.3: IC1.6 16.85,43.52 19.05,45.72 E1.7 19.05,46.99
N$48
  Top 0.3: IC1.7 16.23,44.17 16.51,44.45 E1.6
N$49
  Top 0.3: IC1.8 14.23,44.82 13.97,45.09 E1.5
N$50
  Top 0.3: IC1.9 11.16,44.82 11.43,45.09 E1.4
N$51
  Top 0.3: IC1.10 9.17,44.17 8.89,44.45 E1.3
N$52
  Top 0.3: IC1.11 8.55,43.52 6.35,45.72 E1.2
N$53
  Top 0.3: IC1.12 7.93,42.87 3.81,46.99 E1.1
N$54
  Top 0.3: IC2.5 38.42,42.87 42.55,46.99 E2.8
N$55
  Top 0.3: IC2.6 37.8,43.52 40.01,45.72 E2.7
N$56
  Top 0.3: IC2.7 37.19,44.17 37.47,44.45 E2.6
N$57
  Top 0.3: IC2.8 35.19,44.82 34.92,45.09 E2.5
N$58
  Top 0.3: IC2.9 32.12,44.82 32.38,45.09 E2.4
N$59
  Top 0.3: IC2.10 30.12,44.17 29.84,44.45 E2.3
N$60
  Top 0.3: IC2.11 29.5,43.52 27.3,45.72 E2.2
N$61
  Top 0.3: IC2.12 28.89,42.87 24.77,46.99 E2.1
N$62
  Top 0.3: IC3.5 59.38,42.87 63.5,46.99 E3.8
N$63
  Top 0.3: IC3.6 58.76,43.52 60.96,45.72 E3.7
N$64
  Top 0.3: IC3.7 58.14,44.17 58.42,44.45 E3.6
N$65
  Top 0.3: IC3.8 56.15,44.82 55.88,45.09 E3.5
N$66
  Top 0.3: IC3.9 53.08,44.82 53.34,45.09 E3.4
N$67
  Top 0.3: IC3.10 51.08,44.17 50.8,44.45 E3.3
N$68
  Top 0.3: IC3.11 50.46,43.52 48.26,45.72 E3.2
N$69
  Top 0.3: IC3.12 49.84,42.87 45.72,46.99 E3.1
N$70
  Top 0.3: IC4.5 80.33,42.87 84.45,46.99 E4.8
N$71
  Top 0.3: IC4.6 79.72,43.52 81.92,45.72 E4.7
N$72
  Top 0.3: IC4.7 79.09,44.17 79.38,44.45 E4.6
N$73
  Top 0.3: IC4.8 77.1,44.82 76.83,45.09 E4.5
N$74
  Top 0.3: IC4.9 74.03,44.82 74.3,45.09 E4.4
N$75
  Top 0.3: IC4.10 72.03,44.17 71.75,44.45 E4.3
N$76
  Top 0.3: IC4.11 71.42,43.52 69.22,45.72 E4.2
N$77
  Top 0.3: IC4.12 70.8,42.87 66.67,46.99 E4.1
N$78
  Top 0.3: IC5.5 101.29,42.87 105.41,46.99 E5.8
N$79
  Top 0.3: IC5.6 100.67,43.52 102.87,45.72 E5.7
N$80
  Top 0.3: IC5.7 100.05,44.17 100.33,44.45 E5.6
N$81
  Top 0.3: IC5.8 98.06,44.82 97.79,45.09 E5.5
N$82
  Top 0.3: IC5.9 94.98,44.82 95.25,45.09 E5.4
N$83
  Top 0.3: IC5.10 92.99,44.17 92.71,44.45 E5.3
N$84
  Top 0.3: IC5.11 92.37,43.52 90.17,45.72 E5.2
N$85
  Top 0.3: IC5.12 91.75,42.87 87.63,46.99 E5.1
N$86
  Top 0.3: IC6.5 122.25,42.87 126.36,46.99 E6.8
N$87
  Top 0.3: IC6.6 121.62,43.52 123.83,45.72 E6.7
N$88
  Top 0.3: IC6.7 121,44.17 121.28,44.45 E6.6
N$89
  Top 0.3: IC6.8 119.01,44.82 118.75,45.09 E6.5
N$90
  Top 0.3: IC6.9 115.94,44.82 116.2,45.09 E6.4
N$91
  Top 0.3: IC6.10 113.94,44.17 113.67,44.45 E6.3
N$92
  Top 0.3: IC6.11 113.33,43.52 111.12,45.72 E6.2
N$93
  Top 0.3: IC6.12 112.7,42.87 108.58,46.99 E6.1
N$94
  Top 0.3: IC7.6 142.58,43.52 144.78,45.72 E7.7
N$95
  Top 0.3: IC7.5 143.2,42.87 147.32,46.99 E7.8
N$96
  Top 0.3: IC7.7 141.96,44.17 142.24,44.45 E7.6
N$97
  Top 0.3: IC7.8 139.97,44.82 139.7,45.09 E7.5
N$98
  Top 0.3: IC7.9 136.9,44.82 137.16,45.09 E7.4
N$99
  Top 0.3: IC7.10 134.9,44.17 134.62,44.45 E7.3
N$100
  Top 0.3: IC7.11 134.28,43.52 132.08,45.72 E7.2
N$101
  Top 0.3: IC7.12 133.66,42.87 129.54,46.99 E7.1
N$102
  Top 0.3: IC8.5 164.16,42.87 168.28,46.99 E8.8
N$103
  Top 0.3: IC8.6 163.53,43.52 165.74,45.72 E8.7
N$104
  Top 0.3: IC8.7 162.91,44.17 163.19,44.45 E8.6
N$105
  Top 0.3: IC8.8 160.92,44.82 160.66,45.09 E8.5
N$106
  Top 0.3: IC8.9 157.85,44.82 158.12,45.09 E8.4
N$107
  Top 0.3: IC8.10 155.85,44.17 155.57,44.45 E8.3
N$108
  Top 0.3: IC8.11 155.24,43.52 153.03,45.72 E8.2
N$109
  Top 0.3: IC8.12 154.62,42.87 150.5,46.99 E8.1
N$112
  Bottom 0.3: IC9.16 143.51,19.68 144.78,20.95 EXT..2
N$113
  Bottom 0.3: IC9.17 146.05,17.14 147.32,18.41 EXT..3
N$114
  Bottom 0.3: IC9.18 148.59,14.61 149.86,15.88 EXT..4
N$115
  Bottom 0.3: IC9.19 151.13,12.06 152.4,13.34 EXT..5
OE  (via drill 0.6, 0.6 pad 0.45)
  Top 0.3: IC1.13 6.67,42.22 v4.45,44.45 | IC2.13 27.63,42.22 v25.4,44.45 | IC3.13 48.59,42.22 v46.35,44.45 | IC7.13 132.41,42.22 v130.18,44.45 | IC8.13 153.36,42.22 v151.13,44.45 | IC6.13 111.45,42.22 v109.22,44.45 | IC4.13 69.54,42.22 v67.31,44.45 | IC5.13 90.5,42.22 v88.27,44.45 | IC9.3 110.49,13.34 111.12,13.97 163.83,13.97 165.1,15.24 v165.1,30.48 R28.1
  Bottom 0.3: v4.45,44.45 v25.4,44.45 v46.35,44.45 v67.31,44.45 v88.27,44.45 v109.22,44.45 v130.18,44.45 v151.13,44.45 168.91,44.45 169.54,43.81 169.54,35.56 165.1,31.11 v165.1,30.48
RESET
  Bottom 0.3: R25.1 125.44,14.27 125.73,13.97 C9.2 IC9.9 125.73,6.35 125.09,5.71 109.86,5.71 108.58,4.45 SPI.5
SCK
  Top 0.3: IC9.8 123.19,6.99 122.56,6.35 116.84,6.35 116.2,5.71 SPI.2

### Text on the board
Top: LED Cube | 2010 | v1.0
Drill_legend: Bohrlegende | Datum: 26.09.2010 15:26:57 | 1.0000 mm / 39.370 mil | 0.8000 mm / 31.496 mil | 0.6000 mm / 23.622 mil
